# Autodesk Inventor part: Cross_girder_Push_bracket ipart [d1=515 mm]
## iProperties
Shininess: 69.0
Length Units: 11269
Angle Units: 11279
Time Units: 11290
Mass Units: 11283
Length Display Precision: 3
Angle Display Precision: 2
Created: 2001-06
Part Number: Cross_girder_Push_bracket ipart [d1=515 mm]
Material: Standard
Document SubType Name: Modellieren
Designer: dl
Density: 1 g/cm^3
Density: 0.0
Volumn: 0.0
Area: 0.0
PropertySet Name: Model Information
Control State: 0
Master: False
Checked Out: False
Author: dl
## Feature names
1. TaggingFeature2
